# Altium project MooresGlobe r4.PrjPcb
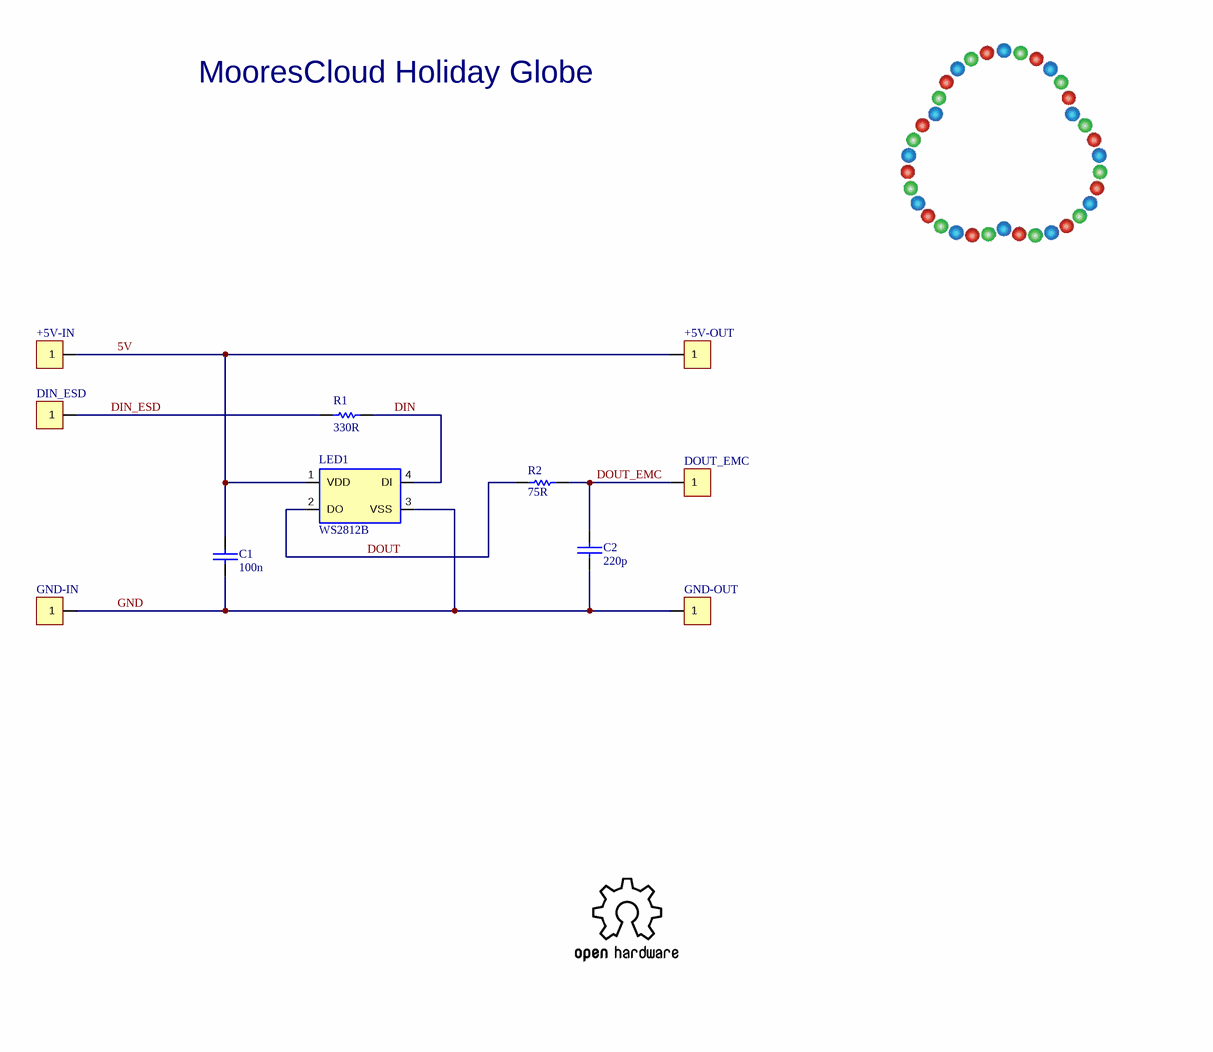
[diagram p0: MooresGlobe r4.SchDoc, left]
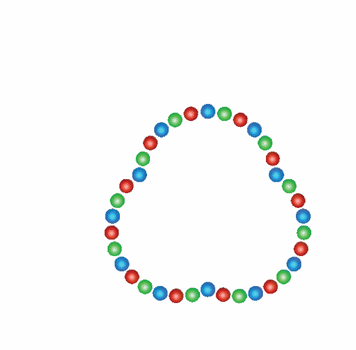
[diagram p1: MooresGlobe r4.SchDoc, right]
1 sheet, 11 parts. Net scope: global (net labels, ports and power ports of the same name join across sheets).
Board files: MooresGlobe r4.PcbDoc, MooresGlobe r4 Panel 10x10.PcbDoc, MooresGlobe r4 Panel 10x10 (no embed).PcbDoc

## Sheet MooresGlobe r4.SchDoc: MooresGlobe for Holiday
size A4; DrawnBy: KJM; Organization: MooresCloud; Revision: 4; SheetNumber: 1; SheetTotal: 1

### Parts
+5V-IN  +5V  [Solder Pad]  (value not drawn)  (no BOM)
+5V-OUT  +5V  [Solder Pad]  (value not drawn)  (no BOM)
C1  100n  [ARA_0603]
C2  220p  [ARA_0603]
DIN_ESD  DIN_ESD  [Solder Pad]  (value not drawn)  (no BOM)
DOUT_EMC  DOUT_EMC  [Solder Pad]  (value not drawn)  (no BOM)
GND-IN  GND  [Solder Pad]  (value not drawn)  (no BOM)
GND-OUT  GND  [Solder Pad]  (value not drawn)  (no BOM)
LED1  WS2812B  [PLCC4-LED]
R1  330R  [ARA_0603]
R2  75R  [ARA_0603]

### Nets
5V: +5V-IN.1 +5V-OUT.1 C1.1 LED1.1(VDD)
DIN: LED1.4(DI) R1.1
DIN_ESD: DIN_ESD.1 R1.2
DOUT: LED1.2(DO) R2.1
DOUT_EMC: C2.1 DOUT_EMC.1 R2.2
GND: C1.2 C2.2 GND-IN.1 GND-OUT.1 LED1.3(VSS)

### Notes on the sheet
- MooresCloud Holiday Globe

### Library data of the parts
+5V-IN +5V-OUT DIN_ESD DOUT_EMC GND-IN GND-OUT = Solder Pad
C1 = CAP: Capacitor Ceramic 100n 50V Y5V 0603; 1.Manufacturer: Yageo; 4.CatNo: 311-1343-2-ND; 5.Note: Ceramic 50V Y5V -20%/+80%; 2.MfgNo: CC0603ZRY5V9BB104; 9.UnitCost: 0.00206
C2 = CAP: Capacitor Ceramic 470p 50V NPO 0603; 1.Manufacturer: Samsung; 4.CatNo: 311-1520-2-ND; 5.Note: Ceramic 50V NP0 5%; 2.MfgNo: CL10C221JB8NNNC; 9.UnitCost: 0.00570
LED1 = WS2812B: WorldSemi WS2812B Smart RGB LED; 9.UnitCost: 0.15
R1 = Res Semi: Resistor 100R 0.1W 5% 0603; 1.Manufacturer: Yageo; 4.CatNo: 311-330GRTR-ND; 2.MfgNo: RC0603JR-07330RL; 9.UnitCost: 0.00092; 5.Note: Thick Film 5% 0.1W
R2 = Res Semi: Resistor 100R 0.1W 5% 0603; 1.Manufacturer: Yageo; 4.CatNo: 311-75GRTR-ND; 2.MfgNo: RC0603JR-0775RL; 9.UnitCost: 0.00092; 5.Note: Thick Film 5% 0.1W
